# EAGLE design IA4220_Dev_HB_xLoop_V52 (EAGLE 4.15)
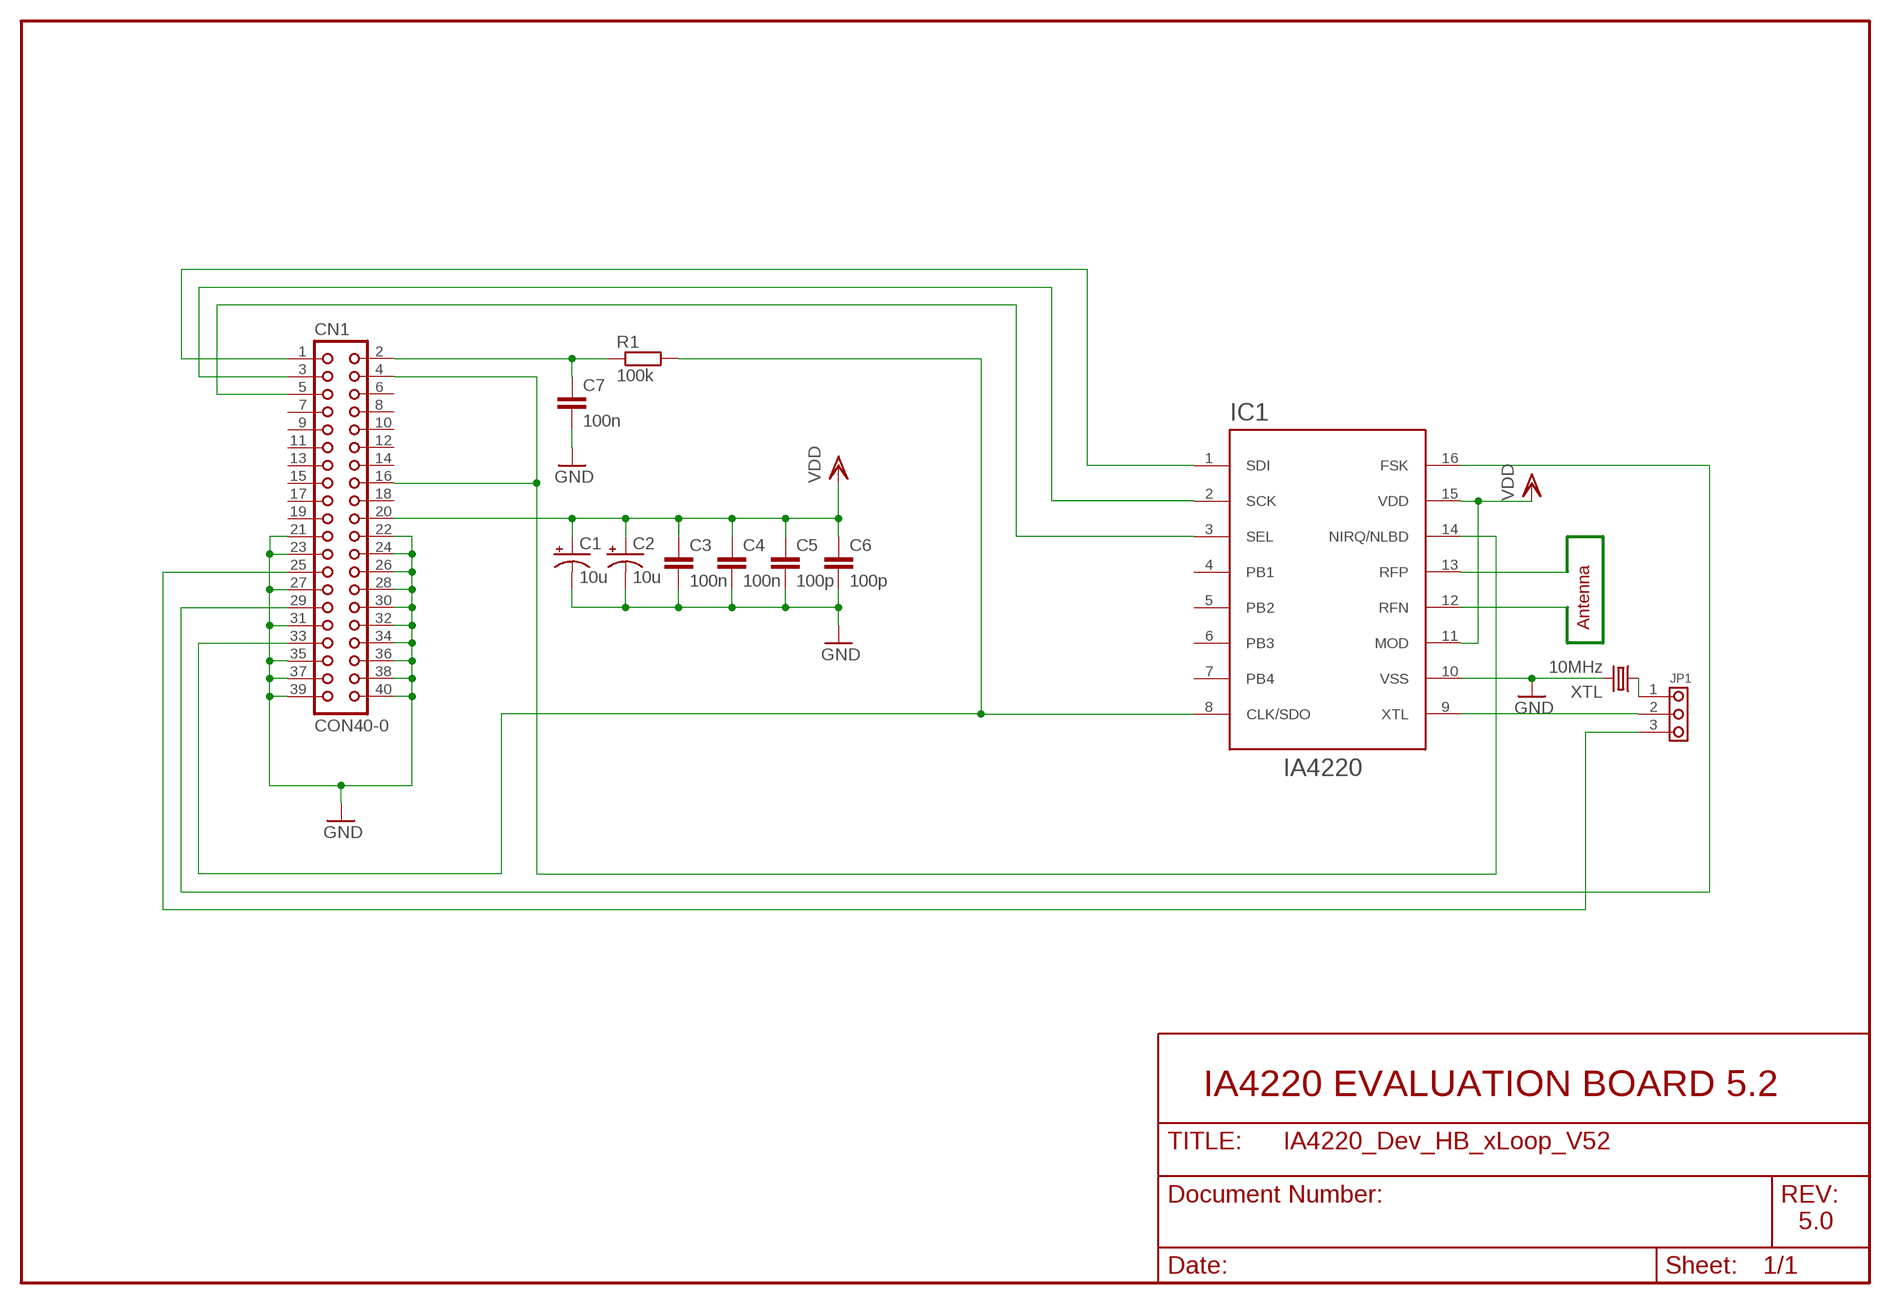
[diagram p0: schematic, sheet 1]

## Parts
C1  10u  CPOL-USA/3216-18R  [A/3216-18R]
C2  10u  CPOL-USA/3216-18R  [A/3216-18R]
C3  100n  C-EUC0603K  [C0603K]
C4  100n  C-EUC0603K  [C0603K]
C5  100p  C-EUC0603K  [C0603K]
C6  100p  C-EUC0603K  [C0603K]
C7  100n  C-EUC0603K  [C0603K]
CN1  CON40-0  [PANDUIT-057-040-0-INTEGRATION]
IC1  IA4220  TINA-TSSOPNEW  [TSSOP-16(NEW)]
JP1  JUMPER3  [PIN3]
R1  100k  R-EU_R0603  [R0603]
XTL  10MHz  SM49  [SM49]

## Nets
GND: C1.- C2.- C3.2 C4.2 C5.2 C6.2 C7.2 CN1.21 CN1.22 CN1.23 CN1.24 CN1.26 CN1.27 CN1.28 CN1.30 CN1.31 CN1.32 CN1.34 CN1.35 CN1.36 CN1.37 CN1.38 CN1.39 CN1.40 IC1.10(VSS) XTL.2
N$1: CN1.3 IC1.2(SCK)
N$2: IC1.12(RFN) IC1.13(RFP)
N$3: CN1.5 IC1.3(SEL)
N$4: CN1.33 IC1.8(CLK/SDO) R1.2
N$5: C7.1 CN1.2 R1.1
N$14: CN1.1 IC1.1(SDI)
N$19: CN1.29 IC1.16(FSK)
N$21: CN1.25 JP1.3
N$24: JP1.1 XTL.1
N$25: IC1.9(XTL) JP1.2
TINA: CN1.4 CN1.16 IC1.14(NIRQ/NLBD)
VDD: C1.+ C2.+ C3.1 C4.1 C5.1 C6.1 CN1.20 IC1.11(MOD) IC1.15(VDD)
Unconnected: CN1.6 CN1.7 CN1.8 CN1.9 CN1.10 CN1.11 CN1.12 CN1.13 CN1.14 CN1.15 CN1.17 CN1.18 CN1.19 IC1.4(PB1) IC1.5(PB2) IC1.6(PB3) IC1.7(PB4)

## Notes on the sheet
- Antenna
- IA4220 EVALUATION BOARD 5.2
- 5.0

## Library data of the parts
C1 C2 = rcl:CPOL-US: POLARIZED CAPACITOR, American symbol
C3-C7 = rcl:C-EU: CAPACITOR, European symbol
CN1 = lve:CON40
IC1 = lve:TINA-TSSOP
JP1 = lve:JUMPER3
R1 = rcl:R-EU_: RESISTOR, European symbol
XTL = crystal:SM49: CRYSTAL

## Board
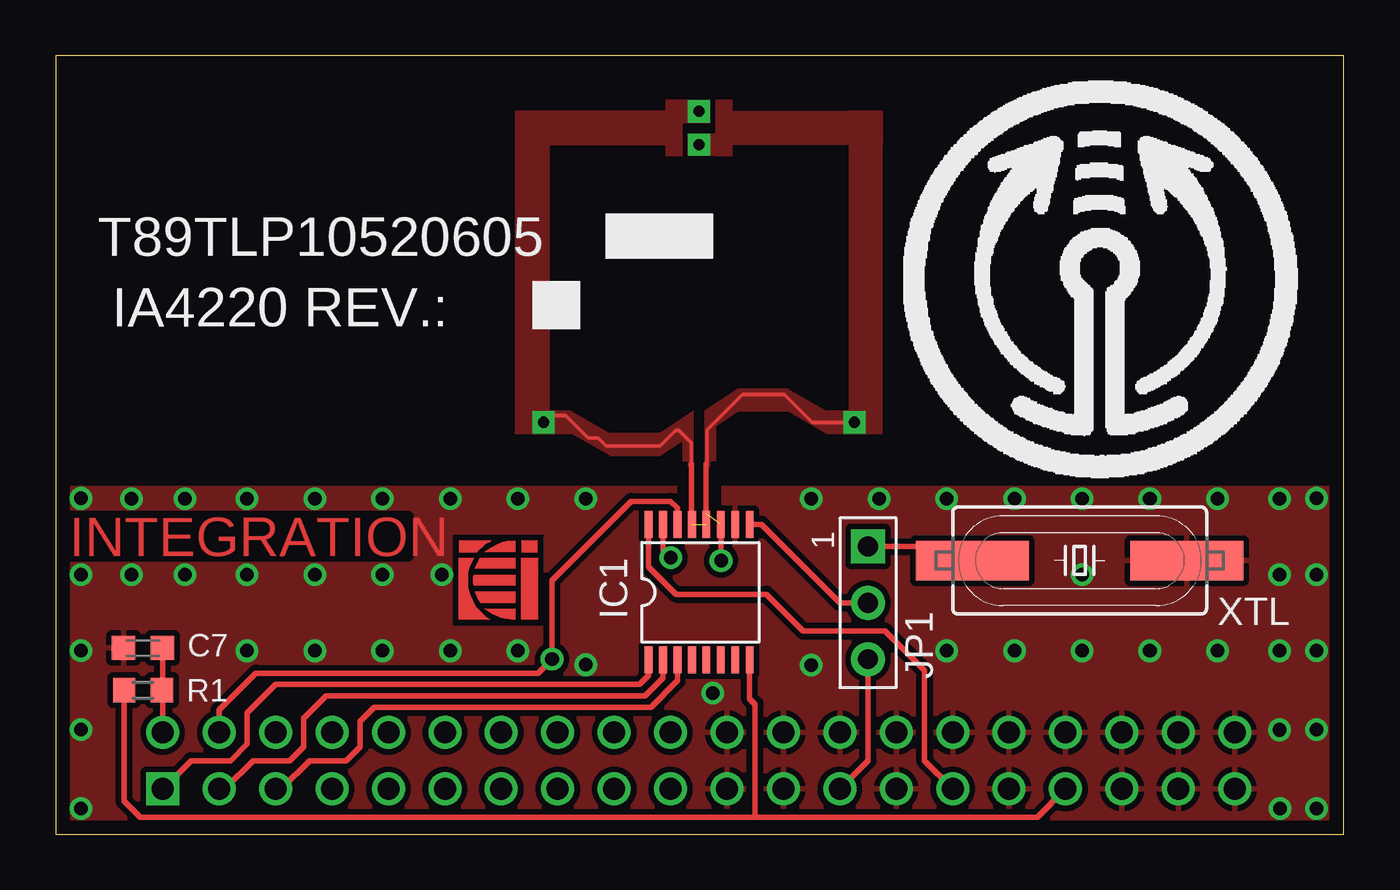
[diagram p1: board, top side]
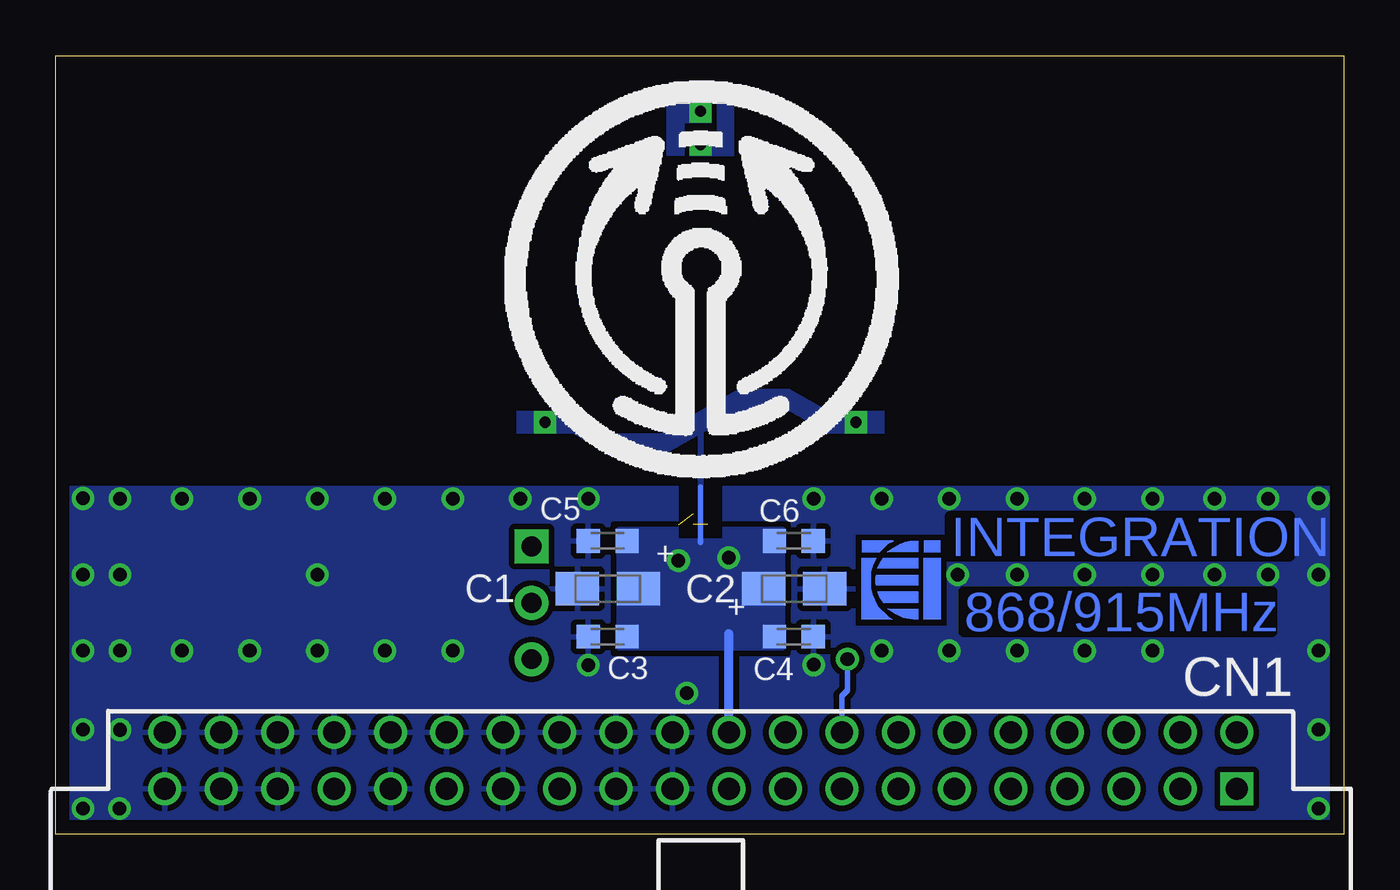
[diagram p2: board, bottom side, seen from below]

Size 58 x 35.05 mm. Coordinates in mm from the lower left corner, seen from the top.
Outline: 0,0 58,0 58,35.05 0,35.05 0,0
Copper layers (1*16): Top 0.035mm / dielectric 1.5mm / Bottom 0.035mm
Design rules "default_INTEGRATION": minimum track width 10mil, minimum drill 20mil, track to track 10mil, track to pad 10mil, pad to pad 10mil, via to via 10mil, smd to smd 10mil, copper to edge 25mil, drill to drill 8mil, minimum pad ring 8mil, minimum via ring 8mil, stop-mask expansion 4mil, vias tented up to drill 35mil, thermal gap 10mil
tRestrict: area 28,13.3 to 29.9,15.7; 3 lines
bRestrict: area 28,13.3 to 29.9,15.7; 4 lines

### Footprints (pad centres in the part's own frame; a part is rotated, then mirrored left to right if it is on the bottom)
A/3216-18R = smd 1.95 x 1.5: + 1.375,0; - -1.375,0
C0603K = smd 1.05 x 1.08: 1 -0.875,0; 2 0.875,0
PANDUIT-057-040-0-INTEGRATION = drill 0.991 square: 1 -24.13,-1.27 | drill 0.991 round: 2 -24.13,-3.81; 3 -21.59,-1.27; 4 -21.59,-3.81; 5 -19.05,-1.27; 6 -19.05,-3.81; 7 -16.51,-1.27; 8 -16.51,-3.81; 9 -13.97,-1.27; 10 -13.97,-3.81; 11 -11.43,-1.27; 12 -11.43,-3.81; 13 -8.89,-1.27; 14 -8.89,-3.81; 15 -6.35,-1.27; 16 -6.35,-3.81; 17 -3.81,-1.27; 18 -3.81,-3.81; 19 -1.27,-1.27; 20 -1.27,-3.81; 21 1.27,-1.27; 22 1.27,-3.81; 23 3.81,-1.27; 24 3.81,-3.81; 25 6.35,-1.27; 26 6.35,-3.81; 27 8.89,-1.27; 28 8.89,-3.81; 29 11.43,-1.27; 30 11.43,-3.81; 31 13.97,-1.27; 32 13.97,-3.81; 33 16.51,-1.27; 34 16.51,-3.81; 35 19.05,-1.27; 36 19.05,-3.81; 37 21.59,-1.27; 38 21.59,-3.81; 39 24.13,-1.27; 40 24.13,-3.81
TSSOP-16(NEW) = smd 1.2 x 0.35: 1 -3.107,2.275; 2 -3.107,1.625; 3 -3.107,0.975; 4 -3.107,0.325; 5 -3.107,-0.325; 6 -3.107,-0.975; 7 -3.107,-1.625; 8 -3.107,-2.275; 9 2.993,-2.275; 10 2.993,-1.625; 11 2.993,-0.975; 12 2.993,-0.325; 13 2.993,0.325; 14 2.993,0.975; 15 2.993,1.625; 16 2.993,2.275
PIN3 = drill 0.889 pad 1.524 square: 1 -2.54,0 | drill 0.889 pad 1.524 round: 2 0,0; 3 2.54,0
R0603 = smd 1 x 1.1: 1 -0.85,0; 2 0.85,0
SM49 = smd 5.08 x 1.778: 1 -4.826,0; 2 4.826,0

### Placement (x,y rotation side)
C1  33.13,11.04 0 bottom
C2  24.75,11.04 180 bottom
C3  33.15,8.89 180 bottom
C4  24.77,8.89 0 bottom
C5  33.15,13.21 180 bottom
C6  24.77,13.21 0 bottom
C7  3.94,8.38 180 top
CN1  28.96,0.76 180 bottom
IC1  28.97,10.95 90 top
JP1  36.58,10.41 270 top
R1  3.94,6.48 180 top
U$1  [LOGO-SMALL]  20.07,11.3 0 top
U$2  [LOGO-SMALL]  19.81,11.3 0 bottom
U$3  [TRANSMIT-ICON]  46.99,25.4 0 top
U$4  [TRANSMIT-ICON]  28.96,25.4 0 bottom
XTL  46.1,12.32 0 top

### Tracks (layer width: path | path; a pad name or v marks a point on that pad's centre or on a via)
GND  (via drill 0.61 pad 1.02)
  other vias: 3.42,15.11 5.83,15.11 8.62,15.11 11.67,15.11 14.72,15.11 17.77,15.11 20.81,15.11 23.86,15.11 3.42,11.68 8.62,8.25 11.67,8.25 14.72,8.25 17.77,8.25 20.81,8.25 5.83,11.68 8.62,11.68 11.67,11.68 14.72,11.68 17.39,11.68 55.1,15.11 52.31,15.11 49.26,15.11 46.21,15.11 43.17,15.11 40.12,15.11 37.07,15.11 34.02,15.11 40.12,8.25 43.17,8.25 46.21,8.25 49.26,8.25 52.31,8.25 55.1,8.25 55.1,11.68 55.1,4.69 29.58,6.34 34.02,7.62 46.21,11.68 1.14,15.11 1.14,11.68 1.14,8.26 1.14,4.7 1.14,1.14 56.77,1.14 56.77,4.7 56.77,8.26 56.77,11.68 56.77,15.11 23.88,7.62 55.12,1.14
  pour Bottom (rank 2): 0.13,0.13 0.13,15.56 57.85,15.56 57.85,0.13
  pour Top: 0.13,0.13 0.13,15.56 57.85,15.56 57.85,0.13
N$1
  Top 0.254: IC1.2 27.34,7.03 26.54,6.22 12.19,6.22 11.18,5.21 11.18,3.94 10.54,3.3 8.89,3.3 7.62,2.03 CN1.3
N$2  (1 unrouted)
  Top 0.254: IC1.13 | IC1.12
N$3
  Top 0.254: IC1.3 28,6.91 26.8,5.71 14.35,5.71 13.72,5.08 13.72,3.94 13.08,3.3 11.43,3.3 10.16,2.03 CN1.5
N$4
  Top 0.254: CN1.33 44.2,0.76 31.5,0.76 | 31.5,0.76 31.5,5.84 31.25,6.09 IC1.8 | R1.2 3.09,1.49 3.81,0.76 31.5,0.76
N$5
  Top 0.254: CN1.2 4.83,6.48 | C7.1 4.83,8.38 4.83,6.48 | 4.83,6.48 R1.1
N$14
  Top 0.254: IC1.1 26.7,7.14 26.29,6.73 9.91,6.73 8.64,5.46 8.64,4.06 7.87,3.3 6.1,3.3 CN1.1
N$19
  Top 0.254: CN1.29 39.12,3.3 39.12,7.37 37.34,9.14 33.66,9.14 32,10.79 27.94,10.79 26.7,12.04 IC1.16
N$21
  Top 0.254: CN1.25 36.58,3.3 JP1.3
N$24
  Top 0.254: XTL.1 40.64,12.95 JP1.1
N$25
  Top 0.254: IC1.9 31.78,13.94 35.31,10.41 JP1.2
TINA  (via drill 0.61 pad 1.02)
  Top 0.254: IC1.14 28,14.68 27.69,14.99 25.91,14.99 22.35,11.43 v22.35,7.87 21.72,7.24 9.02,7.24 7.37,5.59 CN1.4
  Bottom 0.254: CN1.16 22.61,6.22 22.35,6.48 v22.35,7.87
VDD  (via drill 0.5 pad 1, 0.61 pad 1.02)  (1 unrouted)
  Top 0.152: 28.64,16.67 28.64,17.61 28.08,18.17 27.92,18.17 27.21,17.47 24.79,17.47 24.41,17.84 23.96,17.84 22.96,18.85 22.28,18.85 v21.97,18.54 v21.96,18.54 | v35.96,18.54 34.06,18.54 32.81,19.79 30.93,19.79 29.32,18.18 29.32,14.54
  Top 0.25: 28.64,16.67 28.64,14.36 | 29.29,14.44 29.29,16.67
  Top 0.254: v27.7,12.44 27.56,12.57 27.34,12.79 IC1.15 | v29.96,12.31 v29.97,12.31 29.97,12.32 29.95,12.35 IC1.11
  Bottom 0.254: 28.97,13.13 28.97,15.63
  Bottom 0.406: CN1.20 27.69,9.02
  other vias: 28.96,32.54 28.96,31.04
  pour Bottom (no thermals): 25.27,8.38 25.27,13.72 32.64,13.72 32.64,8.38
  pour Top: 29.21,16.54 29.46,16.54 29.46,19.04 29.21,19.04
  pour Bottom: 30.71,17.04 28.96,18.04 28.96,19.04 30.71,18.04
  pour Top: 32.96,20.04 30.71,20.04 30.71,19.04 32.96,19.04
  pour Top: 23.21,19.04 20.71,19.04 20.71,18.04 23.21,18.04
  pour Top: 37.21,18.04 37.21,32.54 35.71,32.54 35.71,18.04
  pour Top: 37.21,19.04 34.71,19.04 34.71,18.04 37.21,18.04
  pour Bottom: 32.96,18.04 30.71,18.04 30.71,17.04 32.96,17.04
  pour Bottom: 32.96,17.04 34.71,18.04 34.71,19.04 32.96,18.04
  pour Top: 32.96,20.04 34.71,19.04 34.71,18.04 32.96,19.04
  pour Top: 29.21,18.04 30.71,19.04 30.71,20.04 29.21,19.04
  pour Bottom: 28.96,18.04 27.21,19.04 27.21,20.04 28.96,19.04
  pour Top: 27.21,17.04 28.71,18.04 28.71,19.04 27.21,18.04
  pour Top: 27.21,18.04 24.96,18.04 24.96,17.04 27.21,17.04
  pour Top: 28.46,16.54 28.71,16.54 28.71,18.79 28.46,18.79
  pour Top: 24.96,17.04 23.21,18.04 23.21,19.04 24.96,18.04
  pour Bottom: 23.21,18.04 24.96,19.04 24.96,20.04 23.21,19.04
  pour Bottom: 27.21,20.04 24.96,20.04 24.96,19.04 27.21,19.04
  pour Bottom: 23.21,19.04 20.71,19.04 20.71,18.04 23.21,18.04
  pour Bottom: 37.21,19.04 34.71,19.04 34.71,18.04 37.21,18.04
  pour Top: 20.71,18.04 20.71,32.54 22.21,32.54 22.21,18.04
  pour Bottom: 28.21,33.04 28.21,30.54 27.46,30.54 27.46,33.04
  pour Bottom: 30.46,33.04 29.71,33.04 29.71,30.54 30.46,30.54
  pour Top: 27.46,33.04 27.46,30.54 28.21,30.54 28.21,33.04
  pour Top: 30.46,33.04 29.71,33.04 29.71,30.54 30.46,30.54
  pour Top: 29.46,33.04 28.21,33.04 28.21,32.04 29.46,32.04
  pour Top: 29.71,31.54 29.71,30.54 28.46,30.54 28.46,31.54
  pour Bottom: 29.71,33.04 29.71,32.04 28.46,32.04 28.46,33.04
  pour Bottom: 29.46,31.54 29.46,30.54 28.21,30.54 28.21,31.54
  pour Top: 20.71,31.04 27.46,31.04 27.46,32.54 20.71,32.54
  pour Top: 37.21,31.04 30.46,31.04 30.46,32.54 37.21,32.54
  pour Top: 29.46,16.79 29.46,19.04 29.71,19.04 29.71,16.79
  pour Top: 28.21,16.79 28.46,16.79 28.46,18.54 28.21,18.54
  pour Bottom: 29.09,13.54 28.84,13.54 28.84,18.54 29.09,18.54

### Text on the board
Top: INTEGRATION
Bottom: INTEGRATION | 868/915MHz
tPlace: T89TLP10520605 | IA4220 REV.: | 1
bPlace: + | +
